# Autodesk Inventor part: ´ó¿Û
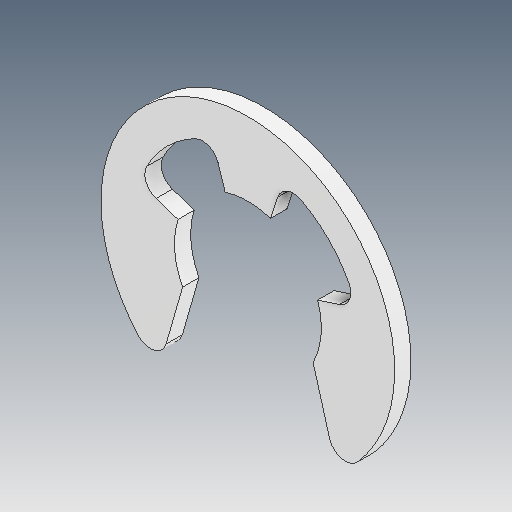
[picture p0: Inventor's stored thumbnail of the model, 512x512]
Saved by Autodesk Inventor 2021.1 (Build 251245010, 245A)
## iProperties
Created: 2021-05
Part Number: ´ó¿Û
Material: Ogólny
Document SubType Name: Modeling
Designer: user
Density: 1 g/cm^3
Appearance: Domyślna
Author: user
Revision Number: ÈÎºÎ
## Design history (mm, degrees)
feature "ÊäÈë1"
node "Bryła1"
